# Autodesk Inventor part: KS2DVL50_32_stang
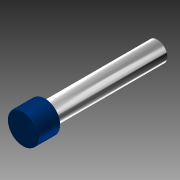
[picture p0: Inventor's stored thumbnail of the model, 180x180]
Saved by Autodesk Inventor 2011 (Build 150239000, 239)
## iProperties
Created: 2010-11
Document SubType Name: Modeling
Designer: TB
Mass: 161.233 g
Surface Area: 236.814 cm^2
Volume: 161.233 cm^3
Density: 1 g/cm^3
Author: TB
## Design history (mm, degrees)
sketch "Sketch2"
  geometry: L1 (-35, -3)-(-35, 3) reference; L2 (-35, -9)-(-35, 9) reference; L3 (-35, 16)-(-253, 16); L4 (-253, 16)-(-253, 0); L5 (-253, 0)-(-35, 0); L6 (-35, 0)-(-35, 16); L7 (-253, 16)-(-216, 16); L8 (-216, 16)-(-216, 25); L9 (-216, 25)-(-253, 25); L10 (-253, 25)-(-253, 16); 1 further point
  constraints: 16 end point, 4 parallel, 2 horizontal, 2 perpendicular, 1 midpoint
  dimensions: "Dia" = 32 diameter of L3 L5; "d3" = 218 distance of L3.start L3.end (computed from Slaglengde, Forlengelse_rør); "StempelDia" = 50 diameter of L9 L5; "StempelLengde" = 37 distance of L8.end L9.end
revolve "Revolution1" sketch "Sketch2" stored, may be unused: angle "d6" = 90 deg
fillet "Fillet1" dims "d7" = 2
sketch "Sketch3"
  geometry: L1 (-253, -23)-(-253, 23) reference; L2 (-253, 0)-(-253.01, 0); L3 (-253, 0)-(-253, 0.01); A1 r 0.01 centre (-253, 0) between (-253, 0.01) and (-253.01, 0); 1 further point
  constraints: 4 end point, 2 point on circle, 1 centre point, 1 midpoint, 1 perpendicular, 1 point on line
  dimensions: "d8" = 0.01 distance of L2.start L2.end; "d9" = 0.01 distance of L2.start L3.end (= d8); "d10" = 0.01 radius of A1 (= d8)
revolve "Revolution2" sketch "Sketch3" stored, may be unused: angle "d11" = 90 deg
body "Solid1"
node "Projected Loop2"
other parameters: "Forlengelse_rør" = 0
